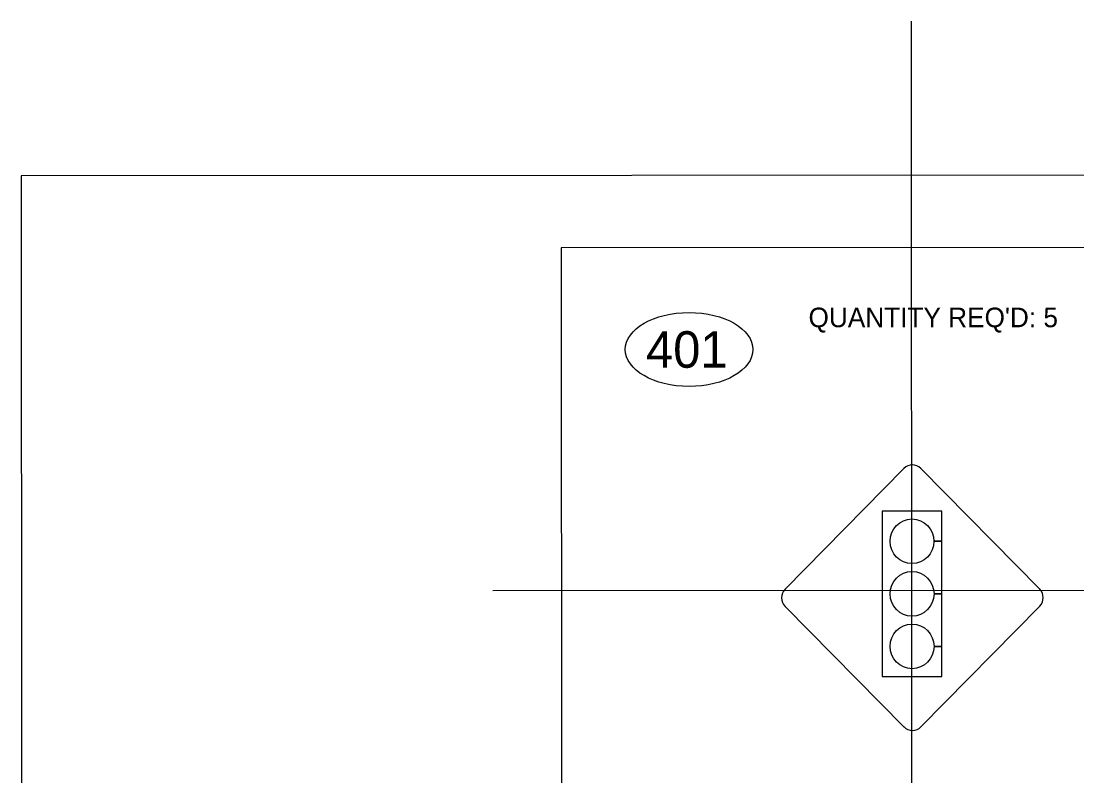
# Model space of a CAD drawing. Extents: x 1977705 to 1981198, y 827296 to 829291.
# Drawn here: x 1979336.7 to 1979660.1, y 828551.8 to 828783 of the extents above; entities that cross this region are included whole.
import ezdxf

# ---------------------------------------------------------------- set-up
doc = ezdxf.new("R2010")
doc.units = 0
for name, color, linetype in [('Level 3', 7, 'Continuous'), ('Level 34', 7, 'Continuous'), ('Level 35', 7, 'Continuous'), ('Level 7', 7, 'Continuous')]:
    doc.layers.add(name, color=color, linetype=linetype)

msp = doc.modelspace()

# ---------------------------------------------------------------- linework, layer by layer
at = {"layer": 'Level 3'}
msp.add_lwpolyline([(1981020.16, 828736.58), (1979336.66, 828735.68), (1979337.25, 827640.68), (1981020.75, 827641.58)], close=True, dxfattribs=at)
at = {"layer": 'Level 34'}
for p, q in [((1979610.04, 827663.85), (1979609.44, 828783.03)), ((1980814.89, 828609.21), (1979481.21, 828608.49))]:
    msp.add_line(p, q, dxfattribs=at)
at = {"layer": 'Level 35'}
for p, q in [((1979607.12, 828645.99), (1979570.74, 828609.01)), ((1979648.74, 828609.06), (1979612.31, 828646)), ((1979570.74, 828603.74), (1979607.16, 828566.8)), ((1979612.35, 828566.81), (1979648.74, 828603.79)), ((1979616.38, 828591.49), (1979616.38, 828591.49))]:
    msp.add_line(p, q, dxfattribs=at)
for points in [[(1979616.36, 828623.7), (1979618.74, 828623.7), (1979618.73, 828632.96), (1979600.49, 828632.95), (1979600.52, 828582.22), (1979618.76, 828582.23), (1979618.75, 828591.49), (1979616.38, 828591.49)], [(1979616.37, 828607.6), (1979618.75, 828607.6), (1979618.74, 828623.7), (1979616.36, 828623.7)], [(1979616.38, 828591.49), (1979618.75, 828591.49), (1979618.75, 828607.6), (1979616.37, 828607.6)]]:
    msp.add_lwpolyline(points, dxfattribs=at)
for centre, major_axis, start_param, end_param in [((1979609.72, 828643.36), (0, 3.73), 5.497787, 7.068583), ((1979609.61, 828623.7), (0, 6.84), 4.712482, 10.995574), ((1979609.62, 828607.59), (0, 6.84), 4.712482, 10.995574), ((1979573.33, 828606.38), (0, 3.73), 0.785398, 2.356194), ((1979646.14, 828606.42), (0, 3.73), 3.926991, 5.497787), ((1979609.63, 828591.49), (0, 6.84), 4.712482, 10.995574), ((1979609.76, 828569.44), (0, 3.73), 2.356194, 3.926991)]:
    msp.add_ellipse(centre, major_axis=major_axis, ratio=0.985005, start_param=start_param, end_param=end_param, dxfattribs=at)
for centre in [(1979609.61, 828623.7), (1979609.62, 828607.59), (1979609.63, 828591.49)]:
    msp.add_ellipse(centre, major_axis=(0, 6.84), ratio=0.985005, dxfattribs=at)
at = {"layer": 'Level 7'}
msp.add_lwpolyline([(1981001.8, 828714.37), (1979502.12, 828713.56), (1979502.69, 827663.79), (1981002.36, 827664.6)], close=True, dxfattribs=at)
msp.add_ellipse((1979541.32, 828682.44), major_axis=(-19.54, 0), ratio=0.580127, dxfattribs=at)

# ---------------------------------------------------------------- texts
msp.add_text("QUANTITY REQ'D: 5", height=6, dxfattribs=at).set_placement((1979577.91, 828689.26))
msp.add_text('401', height=11.202, rotation=359.9962, dxfattribs=at).set_placement((1979528.12, 828676.84))

doc.saveas('drawing.dxf')
